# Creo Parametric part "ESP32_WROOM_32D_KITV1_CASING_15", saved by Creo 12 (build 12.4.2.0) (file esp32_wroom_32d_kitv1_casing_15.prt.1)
Units: Custom; MM, KILOGRAM, SECS

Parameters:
  PTC_WM_ITERATION = "0"
  PTC_WM_VERSION = "-.0"
  PTC_WM_LIFECYCLE_STATE = "In Work"
  PTC_WM_LIFECYCLE = "MO_CADDocument"
  PTC_WM_CREATED_BY = "Maximilian Roepper (Z0017RMS: MO)"
  PTC_WM_CREATED_ON = "18-Sep-26 11:36:42 AM"
  PTC_WM_MODIFIED_BY = "Maximilian Roepper (Z0017RMS: MO)"
  PTC_WM_MODIFIED_ON = "18-Sep-26 11:36:46 AM"
  PDMLINKNUMBER = "PDM000071455028"
  PTC_WM_NAME = "esp32_wroom_32d_kitv1_casing_15.prt"
  PTC_WM_NUMBER = "PDM000071455028"

Other parameters: WEIGHT, WEIGHT_FACTOR, WEIGHT_ADD, _MASS_TEMP, _DIFF_TEMP, MC_ERRORS, SUPPLIER

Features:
  1. coordinate system
  2. datum plane "PRT_YZ"
  3. datum plane "PRT_XY"
  4. datum plane "PRT_XZ"
  5. coordinate system
  6. datum axis
  7. datum axis
  8. datum axis
  9. coordinate system
  10. imported feature
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
Other named items: PRT, SIEMENS_MO, DRW_VIEW_ORG, PRT_X, PRT_Y, PRT_Z, CS0, ROUGH_GROB

Layers: 00_STD_CSYS-KSYS, 01_STD_PLANES-EBENEN, 02_STD_AXES-ACHSEN, 03_STD_CSYS-KSYS, 24_IMPORT_FEAT-IMPORT_KE

Surfaces: 5 plane, 1 cylinder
